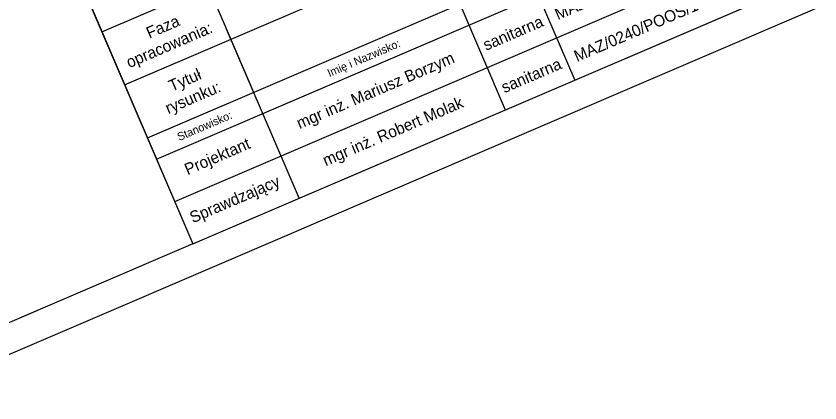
# Model space of a CAD drawing. Extents: x 7500108 to 7500715, y 5768804 to 5769157.
# Drawn here: x 7500588.5 to 7500658.1, y 5768980.6 to 5769014.1 of the extents above; entities that cross this region are included whole.
import ezdxf

# ---------------------------------------------------------------- set-up
doc = ezdxf.new("R2010")
doc.units = 0
for name, color, linetype in [('1_proj_KD_etap3', 7, 'Continuous'), ('_Wydruk', 7, 'Continuous'), ('CMENTARZE_I_POMNIKI', 7, 'Continuous'), ('DZIALKI', 7, 'Continuous'), ('KLASOUZYTKI', 7, 'Continuous')]:
    doc.layers.add(name, color=color, linetype=linetype)

msp = doc.modelspace()

# ---------------------------------------------------------------- linework, layer by layer
at = {"layer": '1_proj_KD_etap3'}
msp.add_lwpolyline([(7500603.806, 5768994.339), (7500172.111, 5768809.112), (7500115.528, 5768940.986), (7500547.223, 5769126.213)], close=True, dxfattribs=at)
at = {"layer": '_Wydruk'}
msp.add_lwpolyline([(7500603.806, 5768994.339), (7500668.134, 5769021.941), (7500650.853, 5769062.216)], dxfattribs=at)
at = {"layer": 'CMENTARZE_I_POMNIKI'}
msp.add_lwpolyline([(7500144.968, 5768872.372), (7500115.528, 5768940.986), (7500547.223, 5769126.213), (7500566.928, 5769080.287), (7500577.052, 5769056.691), (7500603.806, 5768994.339), (7500172.111, 5768809.112), (7500169.246, 5768815.789)], close=True, dxfattribs=at)
at = {"layer": 'DZIALKI'}
for points in [[(7500108.062, 5768940.503), (7500612.863, 5769157.097), (7500671.417, 5769020.629), (7500166.617, 5768804.034)], [(7500115.014, 5768940.765), (7500547.223, 5769126.213), (7500550.885, 5769117.678), (7500586.524, 5769034.615), (7500603.806, 5768994.339), (7500171.597, 5768808.892)]]:
    msp.add_lwpolyline(points, close=True, dxfattribs=at)
at = {"layer": 'KLASOUZYTKI'}
for p, q in [((7500595.919, 5769012.719), (7500660.248, 5769040.32)), ((7500597.891, 5769008.124), (7500652.111, 5769031.388)), ((7500598.869, 5769031.206), (7500609.052, 5769007.472)), ((7500600.651, 5769001.691), (7500664.98, 5769029.292)), ((7500599.862, 5769003.529), (7500654.082, 5769026.793)), ((7500602.228, 5768998.015), (7500656.448, 5769021.279)), ((7500603.806, 5768994.339), (7500658.025, 5769017.603)), ((7500633.138, 5769017.202), (7500636.862, 5769008.522)), ((7500626.905, 5769015.132), (7500630.848, 5769005.942)), ((7500606.686, 5769012.986), (7500612.995, 5768998.282))]:
    msp.add_line(p, q, dxfattribs=at)
msp.add_lwpolyline([(7500603.806, 5768994.339), (7500668.134, 5769021.941), (7500653.956, 5769054.985), (7500589.627, 5769027.383)], close=True, dxfattribs=at)

# ---------------------------------------------------------------- texts
for s, height, p in [('MAZ/0056/POOS/12', 1, (7500635.406, 5769013.723)), ('MAZ/0240/POOS/11', 1, (7500637.064, 5769010.09)), ('Faza', 1, (7500600.025, 5769012.114)), ('sanitarna', 1, (7500629.195, 5769011.067)), ('opracowania:', 1, (7500598.289, 5769009.555)), ('Imię i Nazwisko:', 0.7, (7500615.624, 5769008.784)), ('mgr inż. Mariusz Borzym', 1, (7500613.038, 5769004.285)), ('Tytuł', 1, (7500601.967, 5769007.515)), ('sanitarna', 1, (7500630.772, 5769007.391)), ('rysunku:', 1, (7500601.669, 5769005.574)), ('mgr inż. Robert Molak', 1, (7500615.303, 5769001.064)), ('Stanowisko:', 0.7, (7500602.627, 5769003.246)), ('Projektant', 1, (7500603.339, 5769000.283)), ('Sprawdzający', 1, (7500603.793, 5768996.116))]:
    msp.add_text(s, height=height, rotation=23.22271, dxfattribs=at).set_placement(p)

doc.saveas('drawing.dxf')
